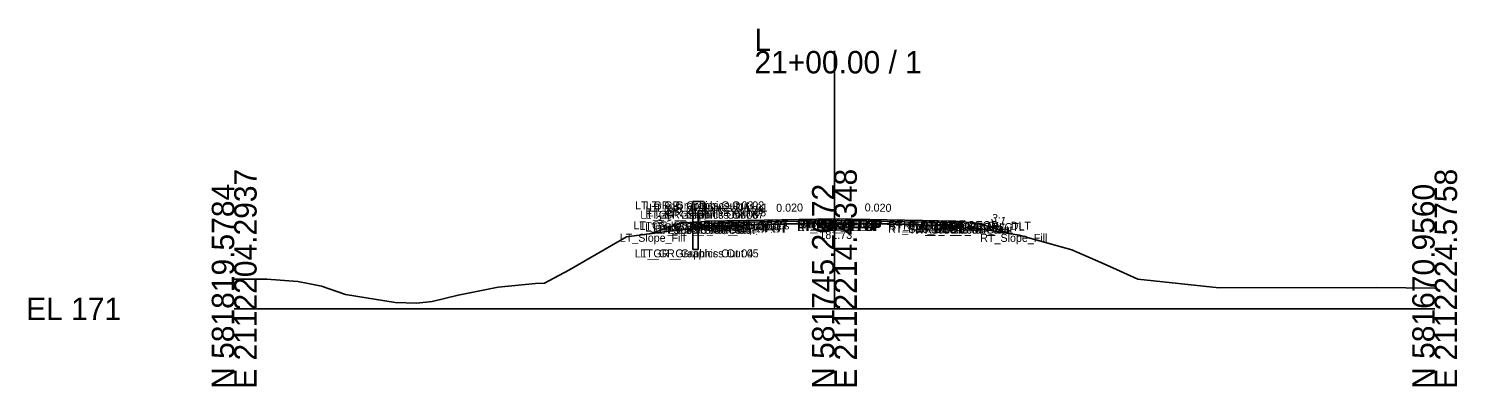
# Model space of a CAD drawing. Extents: x -486 to 1153, y -333 to 9539.
# Drawn here: x 974.3 to 1152.8, y 1990.3 to 2035 of the extents above; entities that cross this region are included whole.
import ezdxf

# ---------------------------------------------------------------- set-up
doc = ezdxf.new("R2010")
doc.units = 0
for name, color, linetype in [('Default', 7, 'Continuous'), ('Exist Cross Section Cell', 7, 'Continuous'), ('Exist XS Ground Line', 7, 'Continuous'), ('Prop CMT Guardrail Graphics', 7, 'Continuous'), ('Prop CMT Pvmt Course 1', 7, 'Continuous'), ('Prop CMT Pvmt Course 2', 7, 'Continuous'), ('Prop CMT Pvmt Course 3', 7, 'Continuous'), ('Prop CMT Pvmt Surface', 7, 'Continuous'), ('Prop CMT Pvmt Surface Shoulder', 7, 'Continuous'), ('Prop CMT Shld Paved Course 1', 7, 'Continuous'), ('Prop CMT Shld Paved Course 2', 7, 'Continuous'), ('Prop CMT Shld Paved Course 3', 7, 'Continuous'), ('Prop CMT Slope Grass', 7, 'Continuous'), ('Prop CMT Subgrade Earthwork', 7, 'Continuous'), ('Prop XS Earthwork Shape', 7, 'Continuous'), ('Prop XS SE Text', 7, 'Continuous'), ('Prop XS Side Slope Text', 7, 'Continuous'), ('Scratch_Level_0', 7, 'Continuous')]:
    doc.layers.add(name, color=color, linetype=linetype)

msp = doc.modelspace()

# ---------------------------------------------------------------- linework, layer by layer
at = {"layer": 'Exist Cross Section Cell'}
for p, q in [((1075, 2000), (1075, 2032.2)), ((1000, 2000), (1075, 2000)), ((1075, 2000), (1150, 2000))]:
    msp.add_line(p, q, dxfattribs=at)
at = {"layer": 'Exist XS Ground Line'}
for p, q in [((1058.86, 2010.14), (1065.34, 2010.54)), ((1065.34, 2010.54), (1071.88, 2010.68)), ((1071.88, 2010.68), (1074.77, 2010.73)), ((1074.77, 2010.73), (1081.85, 2010.61)), ((1081.85, 2010.61), (1084.9, 2010.57)), ((1084.9, 2010.57), (1088.78, 2010.32)), ((1088.78, 2010.32), (1094.05, 2009.87)), ((1041.83, 2004.81), (1049.03, 2008.98)), ((1049.03, 2008.98), (1054.07, 2009.66)), ((1054.07, 2009.66), (1058.86, 2010.14)), ((1094.05, 2009.87), (1098.07, 2009.19)), ((1098.07, 2009.19), (1104.66, 2007.37)), ((1104.66, 2007.37), (1108.93, 2005.48)), ((1108.93, 2005.48), (1112.91, 2003.7)), ((1000, 2003.7), (1004.08, 2003.7)), ((1004.08, 2003.7), (1007.96, 2003.39)), ((1007.96, 2003.39), (1009.26, 2003.14)), ((1009.26, 2003.14), (1010.9, 2002.84)), ((1032.99, 2002.71), (1037.63, 2003.16)), ((1037.63, 2003.16), (1038.77, 2003.19)), ((1038.77, 2003.19), (1041.83, 2004.81)), ((1112.91, 2003.7), (1123.08, 2002.63)), ((1010.9, 2002.84), (1013.9, 2001.79)), ((1013.9, 2001.79), (1020.1, 2000.78)), ((1024.74, 2000.9), (1028, 2001.72)), ((1028, 2001.72), (1032.99, 2002.71)), ((1123.08, 2002.63), (1142.75, 2002.68)), ((1142.75, 2002.68), (1150, 2002.58)), ((1020.1, 2000.78), (1022.82, 2000.71)), ((1022.82, 2000.71), (1024.74, 2000.9))]:
    msp.add_line(p, q, dxfattribs=at)
at = {"layer": 'Prop CMT Guardrail Graphics'}
for points in [[(1057.3, 2007.42), (1057.3, 2013.42)], [(1057.3, 2013.42), (1058.63, 2013.42), (1058.9, 2013.13)], [(1058.9, 2012.54), (1058.63, 2012.25), (1057.96, 2012.25)], [(1057.96, 2012.25), (1057.96, 2007.42)], [(1058.9, 2013.13), (1058.63, 2012.84)], [(1058.63, 2012.84), (1058.9, 2012.54)], [(1057.96, 2007.42), (1057.3, 2007.42)]]:
    msp.add_lwpolyline(points, dxfattribs=at)
at = {"layer": 'Prop CMT Pvmt Course 1'}
for points in [[(1075, 2011.25), (1064, 2011.03)], [(1064, 2010.82), (1075, 2011.04)], [(1064, 2011.03), (1064, 2010.82)], [(1075, 2011.04), (1075, 2011.25)], [(1075, 2011.25), (1086, 2011.03)], [(1075, 2011.04), (1075, 2011.25)], [(1086, 2010.82), (1075, 2011.04)], [(1086, 2011.03), (1086, 2010.82)]]:
    msp.add_lwpolyline(points, dxfattribs=at)
msp.add_lwpolyline([(1075, 2011.04), (1075, 2011.12), (1075, 2011.12), (1075, 2011.04)], close=True, dxfattribs=at)
msp.add_lwpolyline([(1075, 2011.04), (1075, 2011.12), (1075, 2011.12), (1075, 2011.04)], close=True, dxfattribs=at)
at = {"layer": 'Prop CMT Pvmt Course 2'}
for points in [[(1075, 2011.04), (1064, 2010.82)], [(1064, 2010.82), (1064, 2010.49)], [(1064, 2010.49), (1075, 2010.71)], [(1075, 2010.71), (1075, 2011.04)], [(1075, 2010.71), (1075, 2011.04)], [(1075, 2011.04), (1086, 2010.82)], [(1086, 2010.49), (1075, 2010.71)], [(1086, 2010.82), (1086, 2010.49)]]:
    msp.add_lwpolyline(points, dxfattribs=at)
at = {"layer": 'Prop CMT Pvmt Course 3'}
for points in [[(1075, 2010.71), (1064, 2010.49)], [(1064, 2010.49), (1064, 2010.49)], [(1075, 2010.71), (1075, 2010.71)], [(1075, 2010.71), (1086, 2010.49)], [(1075, 2010.71), (1075, 2010.71)], [(1086, 2010.49), (1086, 2010.49)]]:
    msp.add_lwpolyline(points, dxfattribs=at)
at = {"layer": 'Prop CMT Pvmt Surface'}
for points in [[(1075, 2011.25), (1064, 2011.03)], [(1075, 2011.25), (1086, 2011.03)]]:
    msp.add_lwpolyline(points, dxfattribs=at)
at = {"layer": 'Prop CMT Pvmt Surface Shoulder'}
for points in [[(1064, 2011.03), (1059, 2010.93)], [(1086, 2011.03), (1089.95, 2010.95)]]:
    msp.add_lwpolyline(points, dxfattribs=at)
at = {"layer": 'Prop CMT Shld Paved Course 1'}
for points in [[(1064, 2011.03), (1059, 2010.93), (1058.79, 2010.71)], [(1058.79, 2010.71), (1064, 2010.82)], [(1064, 2010.82), (1064, 2011.03)], [(1086, 2011.03), (1089.95, 2010.95), (1090.16, 2010.74)], [(1086, 2010.82), (1086, 2011.03)], [(1090.16, 2010.74), (1086, 2010.82)]]:
    msp.add_lwpolyline(points, dxfattribs=at)
at = {"layer": 'Prop CMT Shld Paved Course 2'}
for points in [[(1064, 2010.82), (1058.79, 2010.71), (1058.45, 2010.37)], [(1058.45, 2010.37), (1064, 2010.49)], [(1064, 2010.49), (1064, 2010.82)], [(1086, 2010.82), (1090.16, 2010.74), (1090.5, 2010.4)], [(1086, 2010.49), (1086, 2010.82)], [(1090.5, 2010.4), (1086, 2010.49)]]:
    msp.add_lwpolyline(points, dxfattribs=at)
at = {"layer": 'Prop CMT Shld Paved Course 3'}
for points in [[(1064, 2010.49), (1058.45, 2010.37)], [(1058.45, 2010.37), (1058.45, 2010.37), (1058.45, 2010.37)], [(1064, 2010.49), (1064, 2010.49)], [(1086, 2010.49), (1090.5, 2010.4)], [(1086, 2010.49), (1086, 2010.49)], [(1090.5, 2010.4), (1090.5, 2010.4), (1090.5, 2010.4)]]:
    msp.add_lwpolyline(points, dxfattribs=at)
at = {"layer": 'Prop CMT Slope Grass'}
for points in [[(1055.9, 2010.68), (1051.94, 2009.37)], [(1058.9, 2010.92), (1055.9, 2010.68)], [(1059, 2010.93), (1058.9, 2010.92)], [(1089.95, 2010.95), (1092.97, 2010.71), (1097.04, 2009.36)]]:
    msp.add_lwpolyline(points, dxfattribs=at)
at = {"layer": 'Prop CMT Subgrade Earthwork'}
for points in [[(1058.45, 2010.37), (1057.98, 2010.85)], [(1064, 2010.49), (1058.45, 2010.37)], [(1075, 2010.71), (1064, 2010.49)], [(1075, 2010.71), (1086, 2010.49)], [(1086, 2010.49), (1090.5, 2010.4)], [(1090.5, 2010.4), (1090.97, 2010.87)]]:
    msp.add_lwpolyline(points, dxfattribs=at)
at = {"layer": 'Prop XS Earthwork Shape'}
for points in [[(1051.94, 2009.37), (1054.07, 2009.66), (1058.86, 2010.14), (1064.72, 2010.5), (1064, 2010.49), (1058.45, 2010.37), (1057.98, 2010.85), (1055.9, 2010.68)], [(1084.9, 2010.57), (1086.25, 2010.48), (1086, 2010.49), (1075, 2010.71), (1064.72, 2010.5), (1065.34, 2010.54), (1071.88, 2010.68), (1074.77, 2010.73), (1081.85, 2010.61)], [(1090.5, 2010.4), (1090.97, 2010.87), (1092.97, 2010.71), (1097.04, 2009.36), (1094.05, 2009.87), (1088.78, 2010.32), (1086.25, 2010.48)]]:
    msp.add_lwpolyline(points, close=True, dxfattribs=at)

# ---------------------------------------------------------------- texts
at = {"layer": 'Default'}
for s, height, p in [('181.73', 1, (1073.12, 2008.73)), ('-', 0.0001, (1000, 2000))]:
    msp.add_text(s, height=height, dxfattribs=at).set_placement(p)
at = {"layer": 'Exist Cross Section Cell'}
for s, p in [('L', (1065, 2032.2)), ('21+00.00 / 1', (1065, 2029.4)), ('EL 171', (974, 1998.6))]:
    msp.add_text(s, height=2.8, dxfattribs=at).set_placement(p)
for s, p in [('E 2112204.2937', (1002.8, 1990)), ('E 2112214.4348', (1077.8, 1990)), ('E 2112224.5758', (1152.8, 1990)), ('N 581819.5784', (1000, 1990)), ('N 581745.2672', (1075, 1990)), ('N 581670.9560', (1150, 1990))]:
    msp.add_text(s, height=2.8, rotation=90, dxfattribs=at).set_placement(p)
at = {"layer": 'Prop XS SE Text'}
for rotation, p in [(1.1458, (1067.73, 2012.1)), (358.8542, (1078.77, 2012.17))]:
    msp.add_text('0.020', height=1, rotation=rotation, dxfattribs=at).set_placement(p)
at = {"layer": 'Prop XS Side Slope Text'}
for rotation, p in [(18.2629, (1052.93, 2010.49)), (341.7371, (1094.49, 2010.99))]:
    msp.add_text('3:1', height=1, rotation=rotation, dxfattribs=at).set_placement(p)
at = {"layer": 'Scratch_Level_0'}
for s, p in [('LT_GR_Graphics Out 03', (1050.08, 2012.42)), ('LT_GR_Graphics Out 06', (1050.74, 2011.25)), ('LT_GR_Graphics Out 07', (1051.39, 2011.25)), ('LT_GR_Graphics Out 09', (1051.4, 2011.84)), ('LT_GR_Graphics Out 02', (1051.43, 2012.42)), ('LT_GR_Graphics Out 08', (1051.67, 2011.54)), ('LT_GR_Graphics Out 01', (1051.85, 2012.13)), ('LT_GS_OS_GR_Face_Graphics', (1049.9, 2009.92)), ('LT_Sub_Trench_Out_DLT', (1050.63, 2009.85)), ('LT_GS_OS_CTL', (1051.36, 2009.68)), ('LT_Sub_Trench_Out', (1052.56, 2009.37)), ('LT_PS3_Shelf_Out', (1053.1, 2009.37)), ('LT_PS3_OEOP', (1054.23, 2009.37)), ('LT_PS2_OEOP', (1054.57, 2009.71)), ('LT_PS1_OEOP', (1054.91, 2009.93)), ('LT_PV2_OEOT', (1059.75, 2009.82)), ('LT_PV3_OEOT', (1059.75, 2009.49)), ('LT_Sub_OEOT', (1059.77, 2009.49)), ('LT_PV1_OEOT', (1059.87, 2010.03)), ('RT_PV2_OEEOP', (1070.33, 2010.04)), ('RT_PV3_OEEOP', (1070.33, 2009.71)), ('RT_Sub_OEEOP', (1070.36, 2009.71)), ('LT_PV2_OEEOP', (1070.39, 2010.04)), ('LT_PV3_OEEOP', (1070.39, 2009.71)), ('LT_Sub_OEEOP', (1070.42, 2009.71)), ('RT_PV1_OEEOP', (1070.45, 2010.12)), ('LT_PV1_OEEOP', (1070.51, 2010.12)), ('RT_PV2_IEEOP', (1070.71, 2010.04)), ('LT_PV2_IEEOP', (1070.77, 2010.04)), ('RT_PV1_IEEOP', (1070.83, 2010.12)), ('LT_PV1_IEEOP', (1070.89, 2010.12)), ('PV2_PGL', (1072.35, 2010.04)), ('PV1_PGL', (1072.47, 2010.25)), ('RT_PV2_OEOT', (1081.69, 2009.82)), ('RT_PV3_OEOT', (1081.69, 2009.49)), ('RT_Sub_OEOT', (1081.71, 2009.49)), ('RT_PV1_OEOT', (1081.81, 2010.03)), ('RT_Sub_Trench_Out_DLT', (1083.56, 2009.87)), ('RT_Sub_Trench_Out', (1084.55, 2009.4)), ('RT_PS3_Shelf_Out', (1085.1, 2009.4)), ('RT_PS1_OEOP', (1085.8, 2009.95)), ('RT_PS2_OEOP', (1085.89, 2009.74)), ('RT_PS3_OEOP', (1086.23, 2009.4)), ('RT_GS_OS_CTL', (1088.37, 2009.71)), ('LT_Slope_Fill', (1048.18, 2008.37)), ('RT_Slope_Fill', (1093.22, 2008.36)), ('LT_GR_Graphics Out 04', (1050.07, 2006.42)), ('LT_GR_Graphics Out 05', (1050.74, 2006.42))]:
    msp.add_text(s, height=1, dxfattribs=at).set_placement(p)

doc.saveas('drawing.dxf')
